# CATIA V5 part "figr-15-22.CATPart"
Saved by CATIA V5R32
Part number: Part1
Bounding box of the stored display mesh (mm): x -75 to 76, y -66.397 to 33.603, z 0 to 100
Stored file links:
  D:\PROJECTS\Project 2022\CATIA V5 6R 2022\Resources\Part Files\c15_catia_v5_6r2022_prt\figr-15-22.CATPart
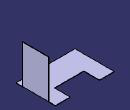
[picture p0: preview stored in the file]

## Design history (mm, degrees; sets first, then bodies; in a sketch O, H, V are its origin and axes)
SheetMetalParameters1: Thickness 1, BendRadius 1, KFactor 0.325257 {= log(min(100,max(20*SheetMetalParameters1.BendRadius,SheetMetalParameters1.Thickness)/SheetMetalParameters1.Thickness))/log(100)/2}, ReliefRadialLength 1, ReliefAxialLength 2, MinimumBendRadius 0
Body1 (main body)
  Sketch1 on xy-plane, origin (0, 0, 0), H (1, 0, 0), V (0, 1, 0)
    line L1 (-37.5, 33.6029) -> (-37.5, -6.3971)
    line L2 (-37.5, -6.3971) -> (37.5, -6.3971)
    line L3 (37.5, -6.3971) -> (37.5, 33.6029)
    line L4 (37.5, 33.6029) -> (75, 33.6029)
    line L5 (75, 33.6029) -> (75, -66.3971)
    line L6 (75, -66.3971) -> (-75, -66.3971)
    line L7 (-75, -66.3971) -> (-75, 33.6029)
    point P8 (-75, 33.6029)
    line L8 (-75, 33.6029) -> (-37.5, 33.6029)
    length L7 = 100
    length L1 = 40
    length L6 = 150
    distance L1 L3 = 75
    vertical: L1 V, L3 V, L5 V, L7 V
    horizontal: L2 H, L4 H, L6 H, L8 H
    coincidence: P8 L4
    symmetry: L7 L5 V, L1 L3 V
  Wall1: Thickness 1, Profile Sketch1
  d_NewWallOnEdge1: NewWallOnEdge_Edge edge [face of Wall1 | face of Wall1], NewWallOnEdge_Length 100, NewWallOnEdge_HeightLimitOffset 0, NewWallOnEdge_WidthOffset1 -16, NewWallOnEdge_WidthOffset2 -17, NewWallOnEdge_Angle 90, NewWallOnEdge_BendRadiusValue 1 {= SheetMetalParameters1.BendRadius}, NewWallOnEdge_BendTable SheetMetalParameters1, KFacteur 0.325257 {= log(min(100,max(20*d_NewWallOnEdge1.Radius,SheetMetalParameters1.Thickness)/SheetMetalParameters1.Thickness))/log(100)/2}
